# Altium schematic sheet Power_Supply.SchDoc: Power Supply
size A4; Date: Not used; ApprovedBy: Not used; CheckedBy: Not used; Author: Not used; CompanyName: STMicroelectronics; DrawnBy: Not used; Engineer: Not used; Organization: Not used; Address1: Not used; Address2: Not used; Address3: Not used; Address4: Not used; DocumentNumber: Not used; Revision: Not used; SheetNumber: 5; SheetTotal: 6
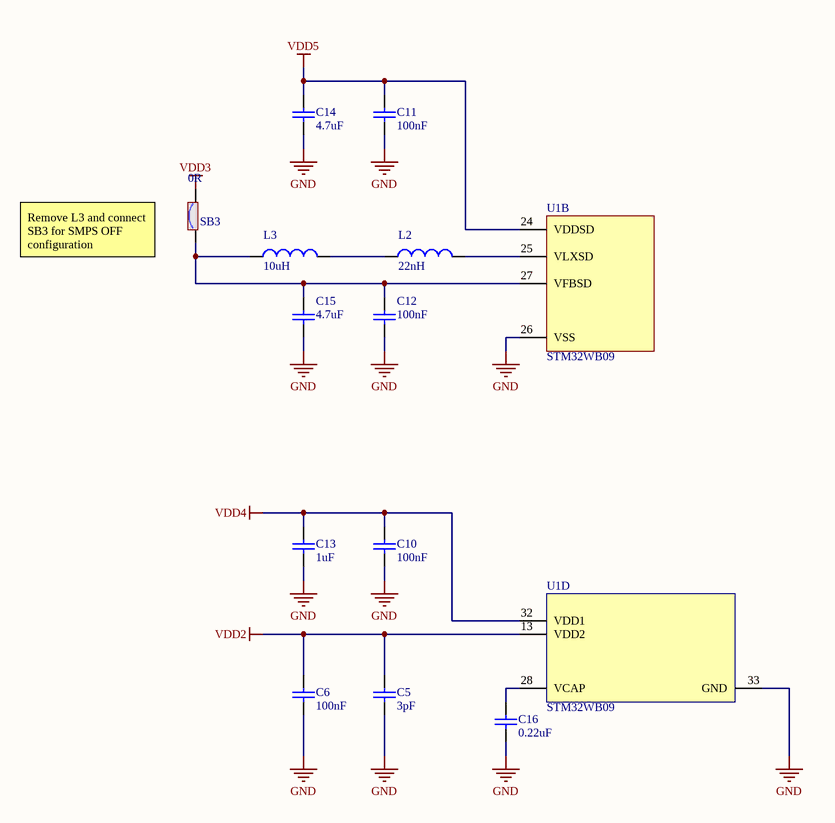
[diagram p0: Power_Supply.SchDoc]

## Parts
C5  value 3pF  [C0402]  (hidden comment: Capacitor)
C6  value 100nF  [C0402]  (hidden comment: Capacitor)
C10  value 100nF  [C0402]  (hidden comment: Capacitor)
C11  value 100nF  [C0402]  (hidden comment: Capacitor)
C12  value 100nF  [C0402]  (hidden comment: Capacitor)
C13  value 1uF  [C0402]  (hidden comment: Capacitor)
C14  value 4.7uF  [C0402]  (hidden comment: Capacitor)
C15  value 4.7uF  [C0402]  (hidden comment: Capacitor)
C16  value 0.22uF  [C0402]  (hidden comment: Capacitor)
L2  value 22nH  [C0402]  (hidden comment: Inductor)
L3  value 10uH  [IND_0805_MURATA_LQM21]  (hidden comment: Inductor)
SB3  value 0R  [SOLDER-BRIDGE_R0402-0R]  (hidden comment: SB_ON)
U1  STM32WB09  [ICC_QFN32-EPAD_5X5_P050]  (parts B,D of 5)

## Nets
GND: C5.1 C6.1 C10.1 C11.1 C12.1 C13.1 C14.1 C15.1 C16.1 U1.26(VSS) U1.33(GND)
VDD2: C5.2 C6.2 U1.13(VDD2)
VDD3: SB3.2
VDD4: C10.2 C13.2 U1.32(VDD1)
VDD5: C11.2 C14.2 U1.24(VDDSD)
NetC12_2: C12.2 C15.2 L3.1 SB3.1 U1.27(VFBSD)
NetC16_2: C16.2 U1.28(VCAP)
NetL2_1: L2.1 L3.2
NetL2_2: L2.2 U1.25(VLXSD)

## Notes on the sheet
- (near SB3) Remove L3 and connect SB3 for SMPS OFF configuration

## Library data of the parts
C5 = MCD-03898: Capacitor, C0G, 3 pF, 50V, NPO, ±0.1pF, 0402, T=0.5mm; Part_Preference: Recommended; Manufacturer: WALSIN TECHNOLOGY CORPORATION; Manufacturer_Part_Number: 0402N3R0B500CT; Order_Code_RS: NA; ShowFields: YES; ID: 6014
C6 C10-C12 = MCD-03442: Capacitor, MLCC, 100nF, ±10%, X7R, 25V, 0402, T=0.5mm; Part_Preference: Recommended; Manufacturer: MURATA; Manufacturer_Part_Number: GRM155R71E104KE14D; Order_Code_RS: NA; ShowFields: YES; ID: 5558; Component_Country_Of_Origin: China, Japan, Philippines, Singapore
C13 = MCD-03432: Capacitor, MLCC, 1uF, X7R, 6.3V, 0402, ± 10%, T=0.5mm; Part_Preference: Recommended; Manufacturer: MURATA; Manufacturer_Part_Number: GRM155R70J105KA12; Order_Code_RS: 113-8711; ShowFields: YES; ID: 5548; Component_Country_Of_Origin: China, Japan, Philippines, Singapore
C14 C15 = MCD-03431: Capacitor, MLCC, 4.7uF, X5R, 10 V, 0402, ± 20%, T=0.5mm; Part_Preference: Recommended; Manufacturer: MURATA; Manufacturer_Part_Number: GRM155R61A475MEAAD; Order_Code_RS: 172-6870; ShowFields: YES; ID: 5547; Component_Country_Of_Origin: China, Japan, Philippines, Singapore
C16 = MCD-03483: Capacitor, MLCC, 0.22uF, X5R, 6.3V, +/-10%, 0402, T=0.5mm; Part_Preference: Recommended; Manufacturer: YAGEO; Manufacturer_Part_Number: CC0402KRX5R5BB224; Order_Code_RS: 3369131; ShowFields: YES; ID: 5599; Component_Country_Of_Origin: China
L2 = MCD-03439: Inductor, MLCC, 22nH, ±2%, 350mA, 0.58R, 0402, T=1.45mm; Part_Preference: Recommended; Manufacturer: MURATA; Manufacturer_Part_Number: LQG15HN22NG02D; Order_Code_RS: 3354168; ShowFields: YES; ID: 5555; Component_Country_Of_Origin: Japan
L3 = MCD-03438: Inductor, MLCC, 10uH, ±20%, 300mA, 845mR, 0805, T=1.45mm; Part_Preference: Recommended; Manufacturer: MURATA; Manufacturer_Part_Number: LQM21DN100M70L; Order_Code_RS: NA; ShowFields: YES; ID: 5554; Component_Country_Of_Origin: Japan
SB3 = MCD-01618: Solder Bridge 0402 ON; Part_Type: Resistor; Part_Preference: Recommended; Manufacturer: YAGEO; Manufacturer_Part_Number: RC0402JR-070RL; Order_Code_RS: 618-5804; Component_Country_Of_Origin: China; ShowFields: YES; ID: 3718
U1 = MCD-03444: Bluetooth® Low Energy wireless SoC; Part_Type: IC; Part_Preference: Recommended; Manufacturer: STMICROELECTRONICS; Component_Country_Of_Origin: Unknown; ShowFields: YES; ID: 5560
